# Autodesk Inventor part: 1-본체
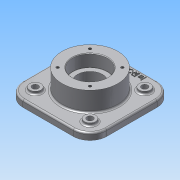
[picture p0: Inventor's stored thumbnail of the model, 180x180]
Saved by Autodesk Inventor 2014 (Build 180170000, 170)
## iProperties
Created: 2015-09
Part Number: 1-본체
Material: 알루미늄 6061
Document SubType Name: Modeling
Designer: study
Density: 2.71 g/cm^3
Appearance: 알루미늄 - 평지
Mass: 1464.68 g
Surface Area: 800.934 cm^2
Volume: 540.471 cm^3
Author: study
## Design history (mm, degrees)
sketch "스케치1"
  geometry: L1 (-75, 75)-(75, 75); L2 (75, 75)-(75, -75); L3 (75, -75)-(-75, -75); L4 (-75, -75)-(-75, 75); L5 (-75, 75)-(75, -75); L6 (75, 75)-(-75, -75); 1 further point
  constraints: 12 end point, 2 midpoint, 2 parallel, 1 horizontal, 1 perpendicular
  dimensions: "d0" = 150 distance of L1.start L1.end; "d1" = 150 distance of L1.end L2.end
extrude "돌출1" new body sketch "스케치1" distance "d2" = 12; taper "d3" = 0 deg
sketch "스케치2"
  geometry: C1 r 50 at (0, 0); 1 further point
  constraints: 1 centre point, 1 coincident
  dimensions: "d4" = 100 diameter of C1
extrude "돌출2" join sketch "스케치2" distance "d5" = 35; taper "d6" = 0 deg
sketch "스케치3"
  geometry: C1 r 50 at (0, 0); 1 further point
  constraints: 1 centre point, 1 coincident
  dimensions: "d7" = 100 diameter of C1
extrude "돌출3" join sketch "스케치3" distance "d8" = 23; taper "d9" = 0 deg
sketch "스케치4"
  geometry: C1 r 50 at (0, 0) reference; 1 further point
  constraints: 1 coincident
hole "구멍1" sketch "스케치4" at (0, 0) diameter "d10" = 45; stored, may be unused: countersink angle "d14" = 90 deg, drill point angle "d16" = 118 deg; dims "d11" = 6, "d12" = 62, "d13" = 22, "d15" = 8
sketch "스케치5"
  geometry: C1 r 50 at (0, 0) reference; 1 further point
  constraints: 1 coincident
hole "구멍2" sketch "스케치5" at (0, 0) diameter "d17" = 45; stored, may be unused: countersink angle "d21" = 90 deg, drill point angle "d23" = 118 deg; dims "d18" = 6, "d19" = 62, "d20" = 22, "d22" = 8
sketch "스케치6"
  geometry: L1 (-49, 49)-(49, 49); L2 (49, 49)-(49, -49); L3 (49, -49)-(-49, -49); L4 (-49, -49)-(-49, 49); L5 (-49, 49)-(49, -49); L6 (49, 49)-(-49, -49); C1 r 50 at (0, 0) reference; C2 r 10 at (-49, 49); C3 r 10 at (49, 49); C4 r 10 at (49, -49); C5 r 10 at (-49, -49)
  constraints: 12 end point, 4 centre point, 4 coincident, 3 equal radius, 2 midpoint, 2 parallel, 1 horizontal, 1 perpendicular
  dimensions: "d24" = 98 distance of L1.start L1.end; "d25" = 98 distance of L1.end L2.end; "d26" = 20 diameter of C2
extrude "돌출4" join sketch "스케치6" distance "d27" = 5; taper "d28" = 0 deg
sketch "스케치7"
  geometry: C1 r 10 at (0, 0) reference; C2 r 10 at (98, 0) reference; C3 r 10 at (0, -98) reference; C4 r 10 at (98, -98) reference; 5 further points
  constraints: 4 coincident
hole "구멍3" sketch "스케치7" at (0, 0), (0, -98), (98, -98), (98, 0) diameter "d29" = 11; stored, may be unused: countersink angle "d33" = 90 deg, drill point angle "d35" = 118 deg; dims "d30" = 6, "d31" = 62, "d32" = 22, "d34" = 8
sketch "스케치8"
  geometry: L1 (-28.991, 28.991)-(28.991, 28.991); L2 (28.991, 28.991)-(28.991, -28.991); L3 (28.991, -28.991)-(-28.991, -28.991); L4 (-28.991, -28.991)-(-28.991, 28.991); L5 (-28.991, 28.991)-(28.991, -28.991); L6 (28.991, 28.991)-(-28.991, -28.991); C1 r 50 at (0, 0) reference; 4 further points
  constraints: 12 end point, 4 coincident, 2 midpoint, 2 parallel, 2 perpendicular, 1 horizontal
  dimensions: "d36" = 82 distance of L1.end L3.end
hole "구멍4" sketch "스케치8" at (-28.991, 28.991), (-28.991, -28.991), (28.991, -28.991), (28.991, 28.991) diameter "d37" = 4.917; stored, may be unused: countersink angle "d41" = 90 deg, drill point angle "d43" = 118 deg; dims "d38" = 10, "d39" = 62, "d40" = 22, "d42" = 13
sketch "스케치9"
  geometry: L1 (-28.991, 28.991)-(28.991, 28.991); L2 (28.991, 28.991)-(28.991, -28.991); L3 (28.991, -28.991)-(-28.991, -28.991); L4 (-28.991, -28.991)-(-28.991, 28.991); L5 (-28.991, 28.991)-(28.991, -28.991); L6 (28.991, 28.991)-(-28.991, -28.991); C1 r 50 at (0, 0) reference; 4 further points
  constraints: 12 end point, 4 coincident, 2 midpoint, 2 parallel, 2 perpendicular, 1 horizontal
  dimensions: "d44" = 82 distance of L1.end L3.end
hole "구멍5" sketch "스케치9" at (-28.991, 28.991), (-28.991, -28.991), (28.991, -28.991), (28.991, 28.991) diameter "d45" = 4.917; stored, may be unused: countersink angle "d49" = 90 deg, drill point angle "d51" = 118 deg; dims "d46" = 10, "d47" = 62, "d48" = 22, "d50" = 13
fillet "모깎기1" dims "d52" = 30
fillet "모깎기2" dims "d53" = 0.3
chamfer "모따기1" distance "d54" = 1; stored, may be unused: second distance "d55" = 2, angle "d56" = 45 deg
fillet "모깎기3" dims "d57" = 3
fillet "모깎기4" dims "d58" = 3
fillet "모깎기5" dims "d59" = 3
sketch "스케치10"
  geometry: C1 r 53 at (0, 0) reference; 1 further point
  constraints: 1 vertical alignment, 1 other
  dimensions: "d60" = 65 distance of C1.centre point (0, 65)
feature "엠보싱1" sketch "스케치10" dims "d61" = 1, "d62" = 0
node "솔리드1"
node "투영된 루프1"
node "투영된 루프2"
node "투영된 루프3"
